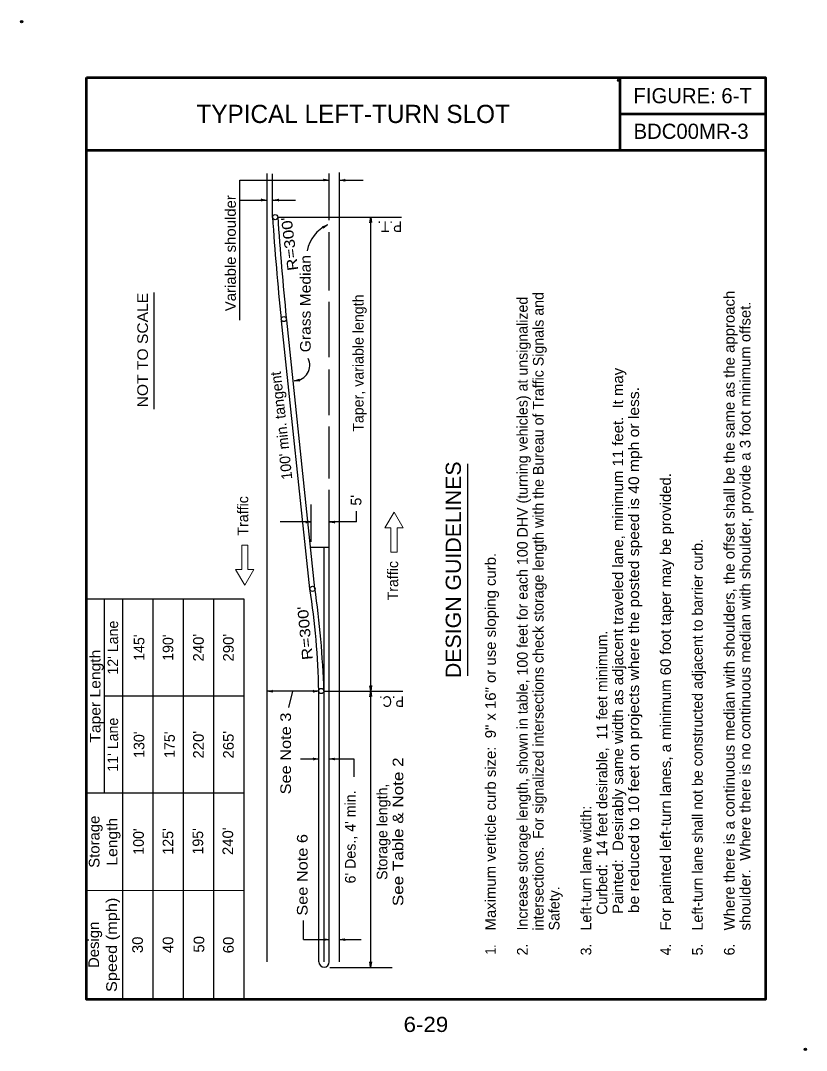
# Model space of a CAD drawing. Extents: x -6.909 to -6.234, y 3.056 to 3.94.
import ezdxf
from ezdxf.enums import TextEntityAlignment as Align

# ---------------------------------------------------------------- set-up
doc = ezdxf.new("R2010")
doc.units = 0
doc.header["$LTSCALE"] = 0.0036
doc.header["$PDMODE"] = 32
doc.header["$PDSIZE"] = 0.0018
doc.layers.add('1', color=7, linetype='Continuous', lineweight=25)
doc.layers.add('60', color=7, linetype='Continuous', lineweight=13)

msp = doc.modelspace()

# ---------------------------------------------------------------- linework, layer by layer
at = {"layer": '1', "lineweight": 53}
for p, q in [((-6.394458, 3.890983), (-6.394458, 3.828483)), ((-6.394458, 3.859733), (-6.269458, 3.859733)), ((-6.852792, 3.828483), (-6.269458, 3.828483))]:
    msp.add_line(p, q, dxfattribs=at)
at = {"layer": '1'}
for p, q in [((-6.697633, 3.131533), (-6.697633, 3.808408)), ((-6.692925, 3.771242), (-6.692925, 3.808325)), ((-6.644375, 3.80285), (-6.64895, 3.802175)), ((-6.6442, 3.768475), (-6.6442, 3.808408)), ((-6.635292, 3.131533), (-6.635292, 3.809267)), ((-6.635183, 3.802808), (-6.630617, 3.803475)), ((-6.635092, 3.802808), (-6.614967, 3.802808)), ((-6.720675, 3.785775), (-6.697633, 3.785775)), ((-6.697833, 3.785717), (-6.702408, 3.785033)), ((-6.692925, 3.785775), (-6.673058, 3.785775)), ((-6.692142, 3.785692), (-6.687575, 3.786383)), ((-6.688375, 3.771158), (-6.582033, 3.771158)), ((-6.608575, 3.1268), (-6.608575, 3.771158)), ((-6.608558, 3.77095), (-6.607883, 3.766383)), ((-6.645667, 3.764467), (-6.649308, 3.761608)), ((-6.6442, 3.70815), (-6.6442, 3.758058)), ((-6.794542, 3.606233), (-6.794542, 3.706367)), ((-6.6442, 3.650808), (-6.6442, 3.698475)), ((-6.660875, 3.451825), (-6.685058, 3.682117)), ((-6.656425, 3.452308), (-6.680625, 3.6826)), ((-6.6442, 3.600908), (-6.6442, 3.640383)), ((-6.674042, 3.630383), (-6.6697, 3.63195)), ((-6.6442, 3.54655), (-6.6442, 3.591233)), ((-6.525192, 3.377175), (-6.525192, 3.55915)), ((-6.6442, 3.131533), (-6.6442, 3.536858)), ((-6.659717, 3.49215), (-6.659717, 3.524258)), ((-6.620783, 3.5093), (-6.620783, 3.518492)), ((-6.659717, 3.5093), (-6.68635, 3.5093)), ((-6.659658, 3.5093), (-6.664242, 3.508608)), ((-6.620783, 3.5093), (-6.6442, 3.5093)), ((-6.644125, 3.509267), (-6.63955, 3.509942)), ((-6.660175, 3.487783), (-6.644075, 3.487783)), ((-6.648658, 3.131533), (-6.648658, 3.487783)), ((-6.717375, 3.443067), (-6.853058, 3.443067)), ((-6.837167, 3.2764), (-6.837167, 3.443067)), ((-6.821542, 3.099317), (-6.821542, 3.443067)), ((-6.7955, 3.099317), (-6.7955, 3.443067)), ((-6.769458, 3.099317), (-6.769458, 3.443067)), ((-6.743417, 3.099317), (-6.743417, 3.443067)), ((-6.717375, 3.099317), (-6.717375, 3.443067)), ((-6.697475, 3.363983), (-6.692892, 3.364658)), ((-6.653667, 3.36395), (-6.697433, 3.36395)), ((-6.679, 3.349942), (-6.67555, 3.36395)), ((-6.653283, 3.363942), (-6.65785, 3.363258)), ((-6.6531, 3.131533), (-6.6531, 3.363442)), ((-6.648717, 3.364108), (-6.58105, 3.364108)), ((-6.608558, 3.364142), (-6.609242, 3.368717)), ((-6.608558, 3.363983), (-6.607883, 3.359408)), ((-6.717375, 3.359733), (-6.837167, 3.359733)), ((-6.668892, 3.305842), (-6.6531, 3.305842)), ((-6.653142, 3.305808), (-6.657725, 3.305117)), ((-6.6442, 3.305842), (-6.623058, 3.305842)), ((-6.644158, 3.30585), (-6.639583, 3.306525)), ((-6.623058, 3.305842), (-6.623058, 3.290567)), ((-6.717375, 3.2764), (-6.853058, 3.2764)), ((-6.852792, 3.193067), (-6.716867, 3.192867)), ((-6.666392, 3.150658), (-6.666392, 3.167067)), ((-6.666392, 3.150658), (-6.6442, 3.150658)), ((-6.644208, 3.150658), (-6.648783, 3.149975)), ((-6.635292, 3.150658), (-6.616717, 3.150658)), ((-6.635258, 3.150658), (-6.630675, 3.151325)), ((-6.608617, 3.126975), (-6.609292, 3.131558)), ((-6.643642, 3.1268), (-6.590125, 3.1268))]:
    msp.add_line(p, q, dxfattribs=at)
at = {"layer": '1', "lineweight": 53}
msp.add_lwpolyline([(-6.852792, 3.890983), (-6.269458, 3.890983), (-6.269458, 3.099317), (-6.852792, 3.099317)], close=True, dxfattribs=at)
at = {"layer": '1'}
for points in [[(-6.720867, 3.6826), (-6.720867, 3.802783), (-6.643992, 3.802783)], [(-6.648175, 3.802842), (-6.649058, 3.803592), (-6.644308, 3.802842)], [(-6.648958, 3.802192), (-6.648175, 3.802817), (-6.648175, 3.802842)], [(-6.631383, 3.802817), (-6.630492, 3.802067), (-6.635242, 3.802817)], [(-6.6306, 3.80345), (-6.631383, 3.802825), (-6.631383, 3.802817)], [(-6.701633, 3.7857), (-6.702517, 3.786442), (-6.697767, 3.7857)], [(-6.702417, 3.785058), (-6.701633, 3.785683), (-6.701633, 3.7857)], [(-6.688342, 3.7857), (-6.68745, 3.784975), (-6.6922, 3.7857)], [(-6.687558, 3.786358), (-6.688342, 3.785725), (-6.688342, 3.7857)], [(-6.60855, 3.767158), (-6.609292, 3.766267), (-6.60855, 3.771008)], [(-6.607892, 3.766367), (-6.608533, 3.767158), (-6.60855, 3.767158)], [(-6.648958, 3.762575), (-6.6501, 3.762775), (-6.645625, 3.764475)], [(-6.649325, 3.761608), (-6.64895, 3.762558), (-6.648958, 3.762575)], [(-6.670333, 3.63115), (-6.669308, 3.6306), (-6.6741, 3.630383)], [(-6.669683, 3.631942), (-6.670333, 3.631175), (-6.670333, 3.63115)], [(-6.663458, 3.509283), (-6.664342, 3.510025), (-6.6596, 3.509283)], [(-6.66425, 3.508633), (-6.663458, 3.509267), (-6.663458, 3.509283)], [(-6.640333, 3.509275), (-6.639433, 3.508525), (-6.644183, 3.509275)], [(-6.63955, 3.509925), (-6.640333, 3.5093), (-6.640333, 3.509275)], [(-6.693667, 3.363992), (-6.692783, 3.363258), (-6.697533, 3.363992)], [(-6.692883, 3.364642), (-6.693667, 3.364017), (-6.693667, 3.363992)], [(-6.657083, 3.363933), (-6.657967, 3.364675), (-6.653217, 3.363933)], [(-6.657867, 3.363275), (-6.657083, 3.363908), (-6.657083, 3.363933)], [(-6.60855, 3.360183), (-6.609292, 3.359283), (-6.60855, 3.364033)], [(-6.609217, 3.368725), (-6.608592, 3.367942), (-6.608575, 3.367942)], [(-6.608575, 3.367942), (-6.607833, 3.368825), (-6.608575, 3.364075)], [(-6.607892, 3.3594), (-6.608533, 3.360183), (-6.60855, 3.360183)], [(-6.656958, 3.3058), (-6.657842, 3.306525), (-6.653092, 3.3058)], [(-6.657742, 3.305142), (-6.656958, 3.305775), (-6.656958, 3.3058)], [(-6.64035, 3.30585), (-6.639467, 3.305108), (-6.644217, 3.30585)], [(-6.639575, 3.306508), (-6.64035, 3.305867), (-6.64035, 3.30585)], [(-6.648008, 3.15065), (-6.648892, 3.151383), (-6.644142, 3.15065)], [(-6.648792, 3.149992), (-6.648008, 3.150633), (-6.648008, 3.15065)], [(-6.631458, 3.150675), (-6.630575, 3.149925), (-6.635308, 3.150675)], [(-6.630675, 3.151308), (-6.631458, 3.150683), (-6.631458, 3.150675)], [(-6.609267, 3.131567), (-6.608642, 3.130783), (-6.608625, 3.130783)], [(-6.608625, 3.130783), (-6.607883, 3.131683), (-6.608625, 3.126933)]]:
    msp.add_lwpolyline(points, dxfattribs=at)
for centre in [(-6.690666, 3.771071), (-6.683211, 3.683549), (-6.65863, 3.451888), (-6.650988, 3.36418)]:
    msp.add_circle(centre, 0.002227, dxfattribs=at)
for centre, radius, start, end in [((-4.163408, 3.939152), 2.53507, 183.7978, 185.78256), ((-3.020529, 4.036638), 3.677519, 184.13894, 185.49412), ((-6.632906, 3.736553), 0.030704, 114.81909, 169.35879), ((-6.674362, 3.644013), 0.013447, 272.55016, 25.32172), ((-7.277009, 3.353803), 0.623892, 0.96849, 9.03945), ((-7.45516, 3.338205), 0.806829, 1.85493, 8.15301), ((-6.648646, 3.131539), 0.004453, 180, 0)]:
    msp.add_arc(centre, radius, start, end, dxfattribs=at)
for p in [(-6.90845, 3.93895), (-6.395542, 3.888525), (-6.235117, 3.05645)]:
    msp.add_point(p, dxfattribs=at)
at = {"layer": '60'}
for points in [[(-6.585908, 3.483383), (-6.591117, 3.483383), (-6.591117, 3.504342), (-6.596325, 3.504342), (-6.588517, 3.517875), (-6.5807, 3.504342), (-6.585908, 3.504342)], [(-6.719408, 3.48945), (-6.7142, 3.48945), (-6.7142, 3.468492), (-6.708992, 3.468492), (-6.7168, 3.454958), (-6.724617, 3.468492), (-6.719408, 3.468492)]]:
    msp.add_lwpolyline(points, close=True, dxfattribs=at)

# ---------------------------------------------------------------- texts
at = {"layer": '1'}
for s, height, p in [('FIGURE: 6-T', 0.01303, (-6.331963, 3.868842)), ('TYPICAL LEFT-TURN SLOT', 0.01562, (-6.623625, 3.851917)), ('BDC00MR-3', 0.01303, (-6.333329, 3.838292))]:
    msp.add_text(s, height=height, dxfattribs=at).set_placement(p, align=Align.CENTER)
for s, height, rotation, width, p in [('Variable shoulder', 0.009117, 90, 1.05, (-6.724433, 3.740092)), ("R=300'", 0.009117, 97.201, 1.2, (-6.673726, 3.748641)), ('P.T.', 0.009117, 180, 0.95, (-6.592238, 3.767483)), ('Grass Median', 0.009117, 90, 1.1, (-6.6601, 3.696763)), ('NOT TO SCALE', 0.009117, 90, 1.1, (-6.79995, 3.656888)), ('DESIGN GUIDELINES', 0.01303, 90, 1.05, (-6.531092, 3.468263)), ("R=300'", 0.009117, 95.527, 1.2, (-6.660427, 3.414323)), ("240'", 0.009108, 90, 1.05, (-6.751983, 3.401396)), ("290'", 0.009108, 90, 1.05, (-6.726267, 3.401396)), ('Taper Length', 0.009117, 90, 1.1, (-6.840717, 3.359733)), ('P.C.', 0.009117, 180, 0.9, (-6.590663, 3.359683)), ('See Note 3', 0.009117, 90, 1.15, (-6.677075, 3.310521)), ("220'", 0.009108, 90, 1.05, (-6.751983, 3.318063)), ("265'", 0.009108, 90, 1.05, (-6.726267, 3.318063)), ('See Table & Note 2', 0.009117, 90, 1.2, (-6.58055, 3.243292)), ('Storage', 0.009117, 90, 1.05, (-6.841567, 3.234754)), ('Length', 0.009117, 90, 1.1, (-6.8262, 3.234754)), ("240'", 0.009108, 90, 1.05, (-6.726767, 3.235171)), ('See Note 6', 0.009117, 90, 1.15, (-6.662792, 3.2063)), ('Speed (mph)', 0.009117, 90, 1.15, (-6.826617, 3.146192)), ('Design', 0.009117, 90, 1.05, (-6.841983, 3.146192)), ('30', 0.009108, 90, 1.05, (-6.804308, 3.146188)), ('40', 0.009108, 90, 1.05, (-6.778142, 3.146188)), ('50', 0.009108, 90, 1.05, (-6.75155, 3.146629)), ('60', 0.009108, 90, 1.05, (-6.726267, 3.146013)), ('1.', 0.009117, 90, 0.85, (-6.501058, 3.1422))]:
    msp.add_text(s, height=height, rotation=rotation, dxfattribs=dict(at, width=width)).set_placement(p, align=Align.CENTER)
for s, p in [('intersections.  For signalized intersections check storage length with the Bureau of Traffic Signals and', (-6.460033, 3.158533)), ('Increase storage length, shown in table, 100 feet for each 100 DHV (turning vehicles) at unsignalized', (-6.473708, 3.158533)), ("5'", (-6.616525, 3.5234)), ('Left-turn lane shall not be constructed adjacent to barrier curb.', (-6.323283, 3.158533)), ('    Curbed:  14 feet desirable,  11 feet minimum.', (-6.405333, 3.158533)), ("6' Des., 4' min.", (-6.621508, 3.198925)), ('Left-turn lane width:', (-6.419008, 3.158533)), ('Safety.', (-6.446358, 3.158533))]:
    msp.add_text(s, height=0.009117, rotation=90, dxfattribs=at).set_placement(p)
for s, width, p in [('Where there is a continuous median with shoulders, the offset shall be the same as the approach', 1.05, (-6.295933, 3.158533)), ('shoulder.  Where there is no continuous median with shoulder, provide a 3 foot minimum offset.', 1.05, (-6.282258, 3.158533)), ('    Painted:  Desirably same width as adjacent traveled lane, minimum 11 feet.  It may', 1.05, (-6.391658, 3.158533)), ('    be reduced to 10 feet on projects where the posted speed is 40 mph or less.', 1.1, (-6.377983, 3.158533)), ('For painted left-turn lanes, a minimum 60 foot taper may be provided.', 1.05, (-6.350633, 3.158533)), ('Maximum verticle curb size:  9" x 16" or use sloping curb.', 1.05, (-6.501058, 3.158533))]:
    msp.add_text(s, height=0.009117, rotation=90, dxfattribs=dict(at, width=width)).set_placement(p)
for s, height, rotation, p in [('Taper, variable length', 0.009117, 90, (-6.614725, 3.645721)), ("100' min. tangent", 0.009117, 96.149, (-6.680853, 3.592528)), ('Traffic', 0.009117, 90, (-6.713783, 3.514525)), ('Traffic', 0.009117, 90, (-6.584958, 3.45885)), ("12' Lane", 0.009108, 90, (-6.82555, 3.4014)), ("145'", 0.009108, 90, (-6.802992, 3.401396)), ("190'", 0.009108, 90, (-6.778142, 3.401396)), ("11' Lane", 0.009108, 90, (-6.82555, 3.318067)), ("130'", 0.009108, 90, (-6.802992, 3.318063)), ("175'", 0.009108, 90, (-6.776842, 3.318063)), ('Storage length,', 0.009117, 90, (-6.594225, 3.243288)), ("100'", 0.009108, 90, (-6.803492, 3.234896)), ("125'", 0.009108, 90, (-6.7782, 3.234988)), ("195'", 0.009108, 90, (-6.752475, 3.235079)), ('2.', 0.009117, 90, (-6.473708, 3.1422)), ('3.', 0.009117, 90, (-6.419008, 3.1422)), ('4.', 0.009117, 90, (-6.350633, 3.1422)), ('5.', 0.009117, 90, (-6.323283, 3.1422)), ('6.', 0.009117, 90, (-6.295933, 3.1422))]:
    msp.add_text(s, height=height, rotation=rotation, dxfattribs=at).set_placement(p, align=Align.CENTER)
at = {"layer": '1', "width": 1.1}
msp.add_text('6-29', height=0.01303, dxfattribs=at).set_placement((-6.561129, 3.071367), align=Align.CENTER)

doc.saveas('drawing.dxf')
